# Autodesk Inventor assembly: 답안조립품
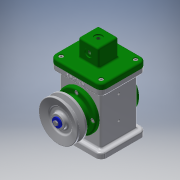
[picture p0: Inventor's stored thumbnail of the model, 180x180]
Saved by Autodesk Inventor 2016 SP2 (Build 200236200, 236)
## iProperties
Created: 2017-08
Part Number: 답안조립품
Document SubType Name: Assembly
Designer: Administrator
Author: Administrator
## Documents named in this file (18)
- D:\470807V1021\답안조립품.iam
- D:\470807V1021\본체.ipt
- D:\470807V1021\덮개.ipt
- D:\470807V1021\앞커버.ipt
- D:\470807V1021\뒤커버.ipt
- D:\470807V1021\편심축.ipt
- D:\470807V1021\베어링 17 x 40 x 12.ipt
- D:\470807V1021\링크.ipt
- D:\470807V1021\슬라이더.ipt
- D:\470807V1021\클레비스 핀 6 x 22.ipt
- 클레비스 핀 6 x 22.ipt
- D:\470807V1021\E-링.ipt
- D:\470807V1021\오일 실 17 30 8.ipt
- D:\470807V1021\키 4 x 4 x 12.ipt
- D:\470807V1021\V-벨트풀리.ipt
- D:\470807V1021\와셔 4x16.ipt
- D:\470807V1021\볼트 M4 x 10.ipt
- D:\470807V1021\볼트 M4 x 8.ipt
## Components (2 placed, 2 different names)
1. E-링:1 — 각도:1
2. V-벨트풀리:1
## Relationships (1: Angle 1)
- 각도:1 [Angle]: E-링:1
